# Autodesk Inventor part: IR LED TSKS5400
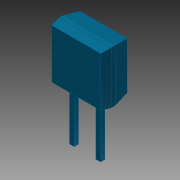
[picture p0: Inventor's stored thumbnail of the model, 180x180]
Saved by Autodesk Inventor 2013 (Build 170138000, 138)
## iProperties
Created: 2012-08
Part Number: IR LED TSKS5400
Material: PC/ABS-Kunststoff
Document SubType Name: Modeling
Designer: rYan
Mass: 0.0905656 g
Surface Area: 1.15542 cm^2
Volume: 0.0606601 cm^3
Density: 1.493 g/cm^3
Author: rYan
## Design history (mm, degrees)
sketch "Skizze2"
  geometry: L1 (-2.253, 1.325)-(2.253, 1.325); L2 (2.5, -0.075)-(2.5, -0.475); L3 (2.35, -1.325)-(-2.35, -1.325); L4 (-2.5, -0.475)-(-2.5, -0.075); L5 (-3.5, 0)-(3.5, 0) reference; L6 (0, 1.855)-(0, -1.855) reference; L7 (2.253, 1.325)-(2.5, -0.075); L8 (2.5, -0.475)-(2.35, -1.325); L9 (-2.253, 1.325)-(-2.5, -0.075); L10 (-2.5, -0.475)-(-2.35, -1.325); 1 further point
  constraints: 16 end point, 2 parallel, 1 horizontal, 1 perpendicular, 4 other
  dimensions: "d5" = 2.65 distance between parallel lines of L3 L1; "d7" = 5 distance between parallel lines of L2 L4; "d8" = 1.4 distance from line of L2.start L1; "d9" = 10 deg angle of L7 L2; "d11" = 10 deg angle of L8 L2; "d12" = 0.4 distance of L2.start L2.end
extrude "Extrusion1" new body sketch "Skizze2" distance "d3" = 5; taper "d4" = 0 deg
sketch "Skizze3"
  geometry: L1 (4.506, -5)-(0, -5) reference; L2 (2.253, -5)-(2.253, 0); L3 (4.506, 0)-(0, 0) reference; C1 r 1.6 at (2.253, -3.1)
  constraints: 2 end point, 1 centre point, 1 midpoint, 1 perpendicular, 1 point on line
  dimensions: "d13" = 3.2 diameter of C1; "d21" = 3.1 distance from line of C1.centre L3
extrude "Extrusion2" cut sketch "Skizze3" distance "d15" = 0.8; taper "d16" = -45 deg
sketch "Skizze4"
  geometry: L1 (0, 0.75)-(0, -0.75); C1 r 0.8 at (0, 0) reference; A1 r 0.75 centre (0, 0) between (0, 0.75) and (0, -0.75); 2 further points
  constraints: 2 coincident, 2 end point, 2 point on circle, 1 centre point, 1 midpoint, 1 vertical
  dimensions: "d17" = 1.5 diameter of A1
revolve "Umdrehung1" sketch "Skizze4" stored, may be unused: angle "d18" = 90 deg
chamfer "Fase1" distance "d22" = 1.4; stored, may be unused: second distance "d23" = 2, angle "d24" = 10 deg
chamfer "Fase2" distance "d25" = 1.4; stored, may be unused: second distance "d26" = 2, angle "d27" = 10 deg
chamfer "Fase3" distance "d28" = 0.8; stored, may be unused: second distance "d29" = 2, angle "d30" = 10 deg
chamfer "Fase4" distance "d31" = 0.8; stored, may be unused: second distance "d32" = 2, angle "d33" = 10 deg
sketch "Skizze5"
  geometry: L1 (-2.5, -0.075)-(2.5, -0.075) reference; L2 (0, -1.855)-(0, 1.855) reference; L3 (-1.495, -0.075)-(-1.045, -0.075); L4 (-1.045, -0.075)-(-1.045, -0.475); L5 (-1.045, -0.475)-(-1.495, -0.475); L6 (-1.495, -0.475)-(-1.495, -0.075); L7 (1.045, -0.075)-(1.495, -0.075); L8 (1.495, -0.075)-(1.495, -0.475); L9 (1.495, -0.475)-(1.045, -0.475); L10 (1.045, -0.475)-(1.045, -0.075); 1 further point
  constraints: 16 end point, 4 parallel, 2 horizontal, 2 perpendicular, 1 collinear, 4 other
  dimensions: "d34" = 0.45 distance of L3.start L3.end; "d36" = 0.4 distance of L3.end L4.end; "d37" = 2.09 distance between parallel lines of L10 L4
extrude "Extrusion3" join sketch "Skizze5" distance "d38" = 5; taper "d39" = 0 deg
node "Volumenkörper1"
